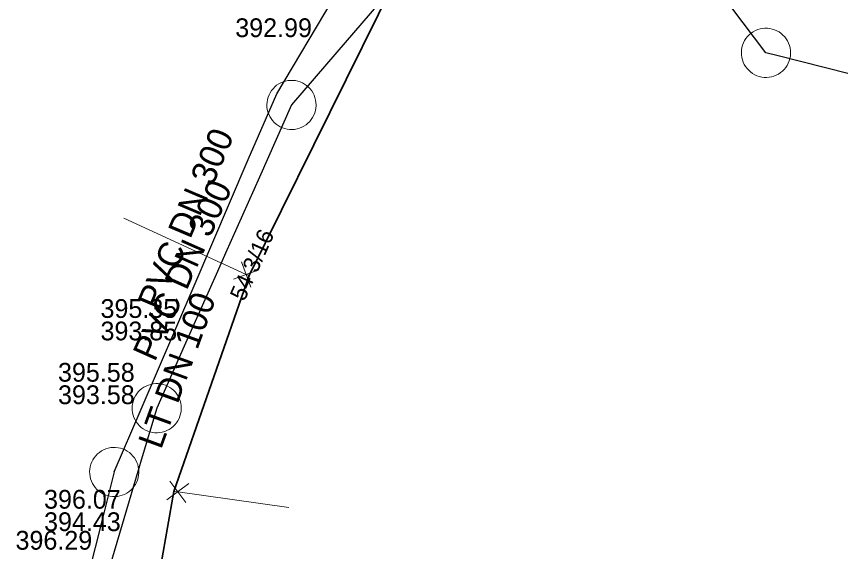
# Model space of a CAD drawing. Extents: x -772952 to -772403, y -1033777 to -1033210.
# Drawn here: x -772811.41 to -772771.85, y -1033366.64 to -1033340.97 of the extents above; entities that cross this region are included whole.
import ezdxf

# ---------------------------------------------------------------- set-up
doc = ezdxf.new("R2010")
doc.units = 0
doc.header["$LTSCALE"] = 0.36
for name, color, linetype, lineweight in [('15', 7, 'Continuous', 13), ('16', 7, 'Continuous', 35), ('2', 7, 'Continuous', 25), ('4', 7, 'Continuous', 13), ('59', 7, 'Continuous', 13)]:
    doc.layers.add(name, color=color, linetype=linetype, lineweight=lineweight)
for name, color, linetype in [('17', 7, 'Continuous'), ('3', 7, 'Continuous'), ('6', 7, 'Continuous')]:
    doc.layers.add(name, color=color, linetype=linetype)

msp = doc.modelspace()

# ---------------------------------------------------------------- linework, layer by layer
at = {"layer": '15'}
for p, q in [((-772800.157, -1033353.949), (-772800.602, -1033352.737)), ((-772799.77, -1033353.119), (-772800.991, -1033353.571)), ((-772804.053, -1033363.257), (-772803.28, -1033364.291)), ((-772804.186, -1033364.163), (-772803.145, -1033363.38))]:
    msp.add_line(p, q, dxfattribs=at)
at = {"layer": '16'}
msp.add_lwpolyline([(-772806.021, -1033377.978), (-772805.954, -1033377.548), (-772805.072, -1033370.662), (-772803.861, -1033363.758), (-772800.241, -1033353.386), (-772792.475, -1033337.699)], dxfattribs=at)
at = {"layer": '2'}
for points in [[(-772774.26, -1033317.38), (-772775.055, -1033318.303), (-772775.793, -1033319.162), (-772776.724, -1033320.243), (-772778.773, -1033322.624), (-772781.051, -1033325.271), (-772783.935, -1033328.623), (-772785.839, -1033330.834), (-772789.162, -1033334.697), (-772791.52, -1033337.436), (-772793.626, -1033339.883), (-772796.031, -1033342.678), (-772798.21, -1033345.21)], [(-772775.43, -1033342.71), (-772784.826, -1033330.263), (-772785.32, -1033329.61)], [(-772806.72, -1033362.82), (-772805.427, -1033359.81), (-772802.883, -1033353.884), (-772800.283, -1033347.83), (-772798.913, -1033344.676), (-772796.212, -1033340.113), (-772795.582, -1033339.048), (-772795.322, -1033338.609), (-772794.79, -1033337.71)], [(-772737.75, -1033352.23), (-772738.982, -1033351.918), (-772739.606, -1033351.761), (-772741.329, -1033351.325), (-772744.293, -1033350.576), (-772747.353, -1033349.803), (-772750.471, -1033349.015), (-772753.362, -1033348.285), (-772760.199, -1033346.558), (-772774.838, -1033342.86), (-772775.43, -1033342.71)], [(-772798.21, -1033345.21), (-772799.75, -1033348.674), (-772801.376, -1033352.329), (-772801.767, -1033353.194), (-772803.359, -1033356.789), (-772804.68, -1033359.76)], [(-772804.68, -1033359.76), (-772805.372, -1033362.098), (-772805.996, -1033364.204), (-772806.588, -1033366.202), (-772807.39, -1033368.91)], [(-772806.72, -1033362.82), (-772807.267, -1033364.982), (-772808.76, -1033370.88)]]:
    msp.add_lwpolyline(points, dxfattribs=at)
at = {"layer": '4'}
for points in [[(-772774.25, -1033342.71), (-772774.256, -1033342.591), (-772774.274, -1033342.474), (-772774.303, -1033342.358), (-772774.344, -1033342.247), (-772774.396, -1033342.14), (-772774.459, -1033342.039), (-772774.532, -1033341.944), (-772774.613, -1033341.858), (-772774.703, -1033341.78), (-772774.801, -1033341.711), (-772774.904, -1033341.653), (-772775.013, -1033341.606), (-772775.127, -1033341.569), (-772775.243, -1033341.544), (-772775.361, -1033341.532), (-772775.48, -1033341.531), (-772775.599, -1033341.542), (-772775.715, -1033341.565), (-772775.829, -1033341.599), (-772775.939, -1033341.645), (-772776.044, -1033341.702), (-772776.142, -1033341.769), (-772776.233, -1033341.845), (-772776.316, -1033341.93), (-772776.39, -1033342.024), (-772776.454, -1033342.124), (-772776.508, -1033342.23), (-772776.551, -1033342.341), (-772776.583, -1033342.455), (-772776.602, -1033342.573), (-772776.61, -1033342.692), (-772776.606, -1033342.81), (-772776.59, -1033342.928), (-772776.562, -1033343.044), (-772776.523, -1033343.156), (-772776.472, -1033343.264), (-772776.411, -1033343.366), (-772776.34, -1033343.462), (-772776.26, -1033343.549), (-772776.171, -1033343.629), (-772776.075, -1033343.699), (-772775.972, -1033343.759), (-772775.864, -1033343.808), (-772775.751, -1033343.846), (-772775.635, -1033343.872), (-772775.517, -1033343.887), (-772775.398, -1033343.89), (-772775.28, -1033343.881), (-772775.162, -1033343.86), (-772775.048, -1033343.827), (-772774.938, -1033343.783), (-772774.832, -1033343.728), (-772774.733, -1033343.662), (-772774.64, -1033343.587), (-772774.556, -1033343.503), (-772774.481, -1033343.411), (-772774.415, -1033343.312), (-772774.359, -1033343.207), (-772774.315, -1033343.097), (-772774.281, -1033342.983), (-772774.26, -1033342.866), (-772774.25, -1033342.747)], [(-772797.029, -1033345.21), (-772797.036, -1033345.091), (-772797.054, -1033344.974), (-772797.083, -1033344.858), (-772797.124, -1033344.747), (-772797.176, -1033344.64), (-772797.239, -1033344.539), (-772797.311, -1033344.444), (-772797.392, -1033344.358), (-772797.483, -1033344.28), (-772797.581, -1033344.211), (-772797.684, -1033344.153), (-772797.793, -1033344.106), (-772797.907, -1033344.069), (-772798.022, -1033344.044), (-772798.141, -1033344.032), (-772798.26, -1033344.031), (-772798.379, -1033344.042), (-772798.495, -1033344.065), (-772798.608, -1033344.099), (-772798.718, -1033344.145), (-772798.823, -1033344.202), (-772798.922, -1033344.269), (-772799.012, -1033344.345), (-772799.096, -1033344.43), (-772799.169, -1033344.524), (-772799.233, -1033344.624), (-772799.288, -1033344.73), (-772799.331, -1033344.841), (-772799.363, -1033344.955), (-772799.382, -1033345.073), (-772799.39, -1033345.192), (-772799.386, -1033345.31), (-772799.37, -1033345.428), (-772799.342, -1033345.544), (-772799.303, -1033345.656), (-772799.252, -1033345.764), (-772799.191, -1033345.866), (-772799.12, -1033345.962), (-772799.039, -1033346.049), (-772798.951, -1033346.129), (-772798.855, -1033346.199), (-772798.752, -1033346.259), (-772798.644, -1033346.308), (-772798.531, -1033346.346), (-772798.414, -1033346.372), (-772798.297, -1033346.387), (-772798.178, -1033346.39), (-772798.059, -1033346.381), (-772797.941, -1033346.36), (-772797.828, -1033346.327), (-772797.718, -1033346.283), (-772797.612, -1033346.228), (-772797.512, -1033346.162), (-772797.419, -1033346.087), (-772797.336, -1033346.003), (-772797.261, -1033345.911), (-772797.195, -1033345.812), (-772797.139, -1033345.707), (-772797.095, -1033345.597), (-772797.061, -1033345.483), (-772797.039, -1033345.366), (-772797.029, -1033345.247)], [(-772803.5, -1033359.76), (-772803.506, -1033359.641), (-772803.524, -1033359.524), (-772803.553, -1033359.408), (-772803.594, -1033359.297), (-772803.646, -1033359.19), (-772803.709, -1033359.089), (-772803.782, -1033358.994), (-772803.863, -1033358.908), (-772803.953, -1033358.83), (-772804.051, -1033358.761), (-772804.154, -1033358.703), (-772804.263, -1033358.656), (-772804.377, -1033358.619), (-772804.493, -1033358.594), (-772804.611, -1033358.582), (-772804.73, -1033358.581), (-772804.849, -1033358.592), (-772804.965, -1033358.615), (-772805.079, -1033358.649), (-772805.189, -1033358.695), (-772805.294, -1033358.752), (-772805.392, -1033358.819), (-772805.483, -1033358.895), (-772805.566, -1033358.98), (-772805.64, -1033359.074), (-772805.704, -1033359.174), (-772805.758, -1033359.28), (-772805.801, -1033359.391), (-772805.833, -1033359.505), (-772805.852, -1033359.623), (-772805.86, -1033359.742), (-772805.856, -1033359.86), (-772805.84, -1033359.978), (-772805.812, -1033360.094), (-772805.773, -1033360.206), (-772805.722, -1033360.314), (-772805.661, -1033360.416), (-772805.59, -1033360.512), (-772805.51, -1033360.599), (-772805.421, -1033360.679), (-772805.325, -1033360.749), (-772805.222, -1033360.809), (-772805.114, -1033360.858), (-772805.001, -1033360.896), (-772804.885, -1033360.922), (-772804.767, -1033360.937), (-772804.648, -1033360.94), (-772804.53, -1033360.931), (-772804.412, -1033360.91), (-772804.298, -1033360.877), (-772804.188, -1033360.833), (-772804.082, -1033360.778), (-772803.983, -1033360.712), (-772803.89, -1033360.637), (-772803.806, -1033360.553), (-772803.731, -1033360.461), (-772803.665, -1033360.362), (-772803.609, -1033360.257), (-772803.565, -1033360.147), (-772803.531, -1033360.033), (-772803.51, -1033359.916), (-772803.5, -1033359.797)], [(-772805.539, -1033362.82), (-772805.546, -1033362.701), (-772805.564, -1033362.584), (-772805.593, -1033362.468), (-772805.634, -1033362.357), (-772805.686, -1033362.25), (-772805.749, -1033362.149), (-772805.821, -1033362.054), (-772805.902, -1033361.968), (-772805.993, -1033361.89), (-772806.091, -1033361.821), (-772806.194, -1033361.763), (-772806.303, -1033361.716), (-772806.417, -1033361.679), (-772806.532, -1033361.654), (-772806.651, -1033361.642), (-772806.77, -1033361.641), (-772806.889, -1033361.652), (-772807.005, -1033361.675), (-772807.119, -1033361.709), (-772807.228, -1033361.755), (-772807.333, -1033361.812), (-772807.432, -1033361.879), (-772807.522, -1033361.955), (-772807.606, -1033362.04), (-772807.679, -1033362.134), (-772807.744, -1033362.234), (-772807.798, -1033362.34), (-772807.841, -1033362.451), (-772807.873, -1033362.565), (-772807.892, -1033362.683), (-772807.9, -1033362.802), (-772807.896, -1033362.92), (-772807.88, -1033363.038), (-772807.852, -1033363.154), (-772807.813, -1033363.266), (-772807.762, -1033363.374), (-772807.701, -1033363.476), (-772807.63, -1033363.572), (-772807.549, -1033363.659), (-772807.461, -1033363.739), (-772807.365, -1033363.809), (-772807.262, -1033363.869), (-772807.154, -1033363.918), (-772807.041, -1033363.956), (-772806.924, -1033363.982), (-772806.807, -1033363.997), (-772806.688, -1033364), (-772806.57, -1033363.991), (-772806.451, -1033363.97), (-772806.338, -1033363.937), (-772806.228, -1033363.893), (-772806.122, -1033363.838), (-772806.022, -1033363.772), (-772805.929, -1033363.697), (-772805.846, -1033363.613), (-772805.771, -1033363.521), (-772805.705, -1033363.422), (-772805.649, -1033363.317), (-772805.605, -1033363.207), (-772805.571, -1033363.093), (-772805.549, -1033362.976), (-772805.539, -1033362.857)]]:
    msp.add_lwpolyline(points, close=True, dxfattribs=at)
at = {"layer": '59'}
for points in [[(-772800.241, -1033353.386), (-772800.38, -1033353.345), (-772806.261, -1033350.64)], [(-772803.861, -1033363.759), (-772803.667, -1033363.773), (-772798.333, -1033364.526)]]:
    msp.add_lwpolyline(points, dxfattribs=at)

# ---------------------------------------------------------------- texts
at = {"layer": '17'}
msp.add_text('LT DN 100 ', height=1.2, rotation=70, dxfattribs=at).set_placement((-772804.472, -1033361.777))
at = {"layer": '3'}
for s, height, rotation, p in [('PVC DN 300', 1.2, 67, (-772804.535, -1033355.132)), ('PVC DN 300', 1.2, 66, (-772804.77, -1033357.572)), ('54 3/16', 0.8, 66, (-772800.471, -1033354.667))]:
    msp.add_text(s, height=height, rotation=rotation, dxfattribs=at).set_placement(p)
at = {"layer": '6'}
for s, p in [('392.99', (-772800.909, -1033341.956)), ('395.35', (-772807.378, -1033355.428)), ('393.85', (-772807.378, -1033356.505)), ('395.58', (-772809.418, -1033358.487)), ('393.58', (-772809.418, -1033359.564)), ('396.07', (-772810.088, -1033364.579)), ('394.43', (-772810.088, -1033365.656)), ('396.29', (-772811.458, -1033366.547))]:
    msp.add_text(s, height=0.9, dxfattribs=at).set_placement(p)

doc.saveas('drawing.dxf')
